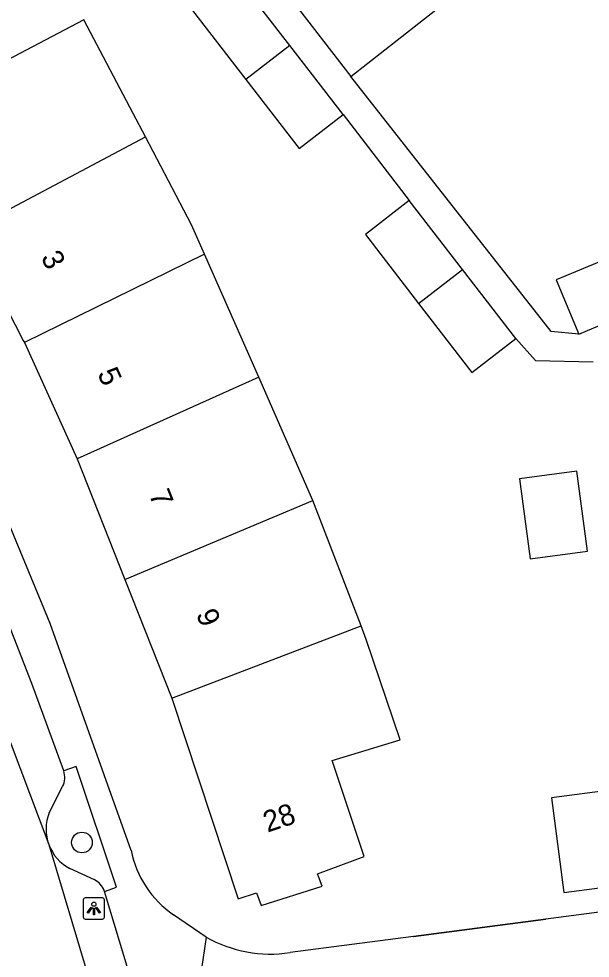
# Model space of a CAD drawing. Extents: x 162074 to 163034, y 381824 to 382557.
# Drawn here: x 162339.63 to 162366.61, y 382465.37 to 382509.72 of the extents above; entities that cross this region are included whole.
import ezdxf

# ---------------------------------------------------------------- set-up
doc = ezdxf.new("R2010")
doc.units = 0
for name, color, linetype in [('IMGEO_Boom', 7, 'Continuous'), ('IMGEO_Lichtpunt', 7, 'Continuous'), ('IMGEO_Muur', 7, 'Continuous'), ('IMGEO_Pand', 7, 'Continuous'), ('IMGEO_Pand_nummerreeks', 7, 'Continuous'), ('IMGEO_Parkeervlak_open', 7, 'Continuous'), ('IMGEO_Rijbaan_lokaal_gesloten', 7, 'Continuous'), ('IMGEO_Voetpad_open', 7, 'Continuous')]:
    doc.layers.add(name, color=color, linetype=linetype)

msp = doc.modelspace()

# ---------------------------------------------------------------- linework, layer by layer
at = {"layer": 'IMGEO_Boom'}
msp.add_circle((162342.613, 382470.834), 0.489, dxfattribs=at)
at = {"layer": 'IMGEO_Lichtpunt'}
for p, q in [((162342.677, 382468.123), (162342.677, 382467.316)), ((162342.677, 382468.123), (162342.677, 382467.316)), ((162343.579, 382468.218), (162342.771, 382468.218)), ((162343.579, 382468.218), (162342.771, 382468.218)), ((162343.673, 382467.316), (162343.673, 382468.123)), ((162343.673, 382467.316), (162343.673, 382468.123)), ((162342.771, 382467.222), (162343.579, 382467.222)), ((162342.771, 382467.222), (162343.579, 382467.222))]:
    msp.add_line(p, q, dxfattribs=at)
for points in [[(162343.051, 382467.787), (162343.09, 382467.759), (162342.902, 382467.497), (162342.864, 382467.524), (162343.051, 382467.787)], [(162343.153, 382467.739), (162343.2, 382467.739), (162343.2, 382467.417), (162343.153, 382467.417), (162343.153, 382467.739)], [(162343.263, 382467.759), (162343.301, 382467.786), (162343.488, 382467.524), (162343.449, 382467.496), (162343.263, 382467.759)]]:
    msp.add_lwpolyline(points, dxfattribs=at)
msp.add_circle((162343.176, 382467.921), 0.0994, dxfattribs=at)
for centre, start, end in [((162342.771, 382468.123), 90, 180), ((162342.771, 382468.123), 90, 180), ((162343.579, 382468.123), 0, 90), ((162343.579, 382468.123), 0, 90), ((162342.771, 382467.316), 180, 270), ((162342.771, 382467.316), 180, 270), ((162343.579, 382467.316), 270, 0), ((162343.579, 382467.316), 270, 360)]:
    msp.add_arc(centre, 0.0946, start, end, dxfattribs=at)
at = {"layer": 'IMGEO_Muur'}
msp.add_lwpolyline([(162358.274, 382466.401), (162364.52, 382467.221)], dxfattribs=at)
at = {"layer": 'IMGEO_Pand'}
for points in [[(162349.248, 382514.857), (162352.301, 382510.897), (162355.304, 382507)], [(162349.916, 382511.715), (162347.84, 382510.115), (162350.351, 382506.857)], [(162352.427, 382508.458), (162349.916, 382511.715)], [(162355.304, 382507), (162360.118, 382510.786)], [(162345.614, 382504.148), (162345.035, 382505.25), (162342.711, 382509.677), (162334.255, 382505.237), (162334.806, 382504.186), (162334.186, 382503.86), (162335.566, 382501.232), (162336.213, 382501.572), (162337.025, 382500), (162337.188, 382499.684)], [(162352.427, 382508.458), (162350.351, 382506.857)], [(162354.939, 382505.198), (162352.427, 382508.458)], [(162350.351, 382506.857), (162352.863, 382503.598), (162354.939, 382505.198)], [(162337.188, 382499.684), (162337.784, 382500), (162345.614, 382504.148)], [(162348.404, 382498.607), (162347.791, 382500), (162345.614, 382504.148)], [(162358.069, 382501.145), (162355.993, 382499.545), (162358.505, 382496.287)], [(162360.58, 382497.888), (162358.069, 382501.145)], [(162337.188, 382499.684), (162339.847, 382494.541), (162339.895, 382494.435)], [(162368.715, 382498.945), (162365.914, 382497.774), (162365.006, 382497.395), (162366.074, 382494.84)], [(162348.404, 382498.607), (162339.895, 382494.435)], [(162350.957, 382492.801), (162348.404, 382498.607)], [(162358.505, 382496.287), (162360.58, 382497.888)], [(162363.092, 382494.628), (162360.58, 382497.888)], [(162358.505, 382496.287), (162361.016, 382493.028), (162363.092, 382494.628)], [(162366.074, 382494.84), (162369.808, 382496.402)], [(162339.895, 382494.435), (162342.396, 382488.941)], [(162350.957, 382492.801), (162342.396, 382488.941)], [(162353.515, 382486.987), (162350.957, 382492.801)], [(162342.396, 382488.941), (162344.642, 382483.25)], [(162363.769, 382484.234), (162366.474, 382484.587), (162365.982, 382488.359), (162363.277, 382488.006), (162363.769, 382484.234)], [(162344.642, 382483.25), (162353.515, 382486.987)], [(162355.79, 382481.061), (162353.515, 382486.987)], [(162344.642, 382483.25), (162346.852, 382477.646)], [(162346.852, 382477.646), (162355.79, 382481.061)], [(162346.852, 382477.646), (162349.986, 382468.167), (162350.847, 382468.463), (162351.075, 382467.853), (162353.947, 382468.78), (162353.729, 382469.361), (162355.932, 382470.181), (162354.43, 382474.706), (162357.631, 382475.682), (162356.035, 382480.422), (162355.79, 382481.061)], [(162365.36, 382468.479), (162368.129, 382468.84), (162367.545, 382473.312), (162364.776, 382472.95), (162365.36, 382468.479)]]:
    msp.add_lwpolyline(points, dxfattribs=at)
at = {"layer": 'IMGEO_Parkeervlak_open'}
for points in [[(162341.072, 382472.235), (162341.7, 382473.471)], [(162343.204, 382469.075), (162342.049, 382469.609)], [(162343.672, 382468.517), (162343.658, 382468.564)]]:
    msp.add_lwpolyline(points, dxfattribs=at)
for centre, radius, start, end in [((162340.864, 382473.906), 0.942, 332.5041, 19.39), ((162342.997, 382471.457), 2.076, 157.9974, 200.321), ((162343.002, 382471.46), 2.082, 200.3477, 242.7614), ((162342.787, 382468.247), 0.927, 19.9834, 63.2558)]:
    msp.add_arc(centre, radius, start, end, dxfattribs=at)
at = {"layer": 'IMGEO_Rijbaan_lokaal_gesloten'}
for points in [[(162335.462, 382485.538), (162341.05, 382470.736)], [(162341.05, 382470.736), (162343.943, 382461.05)]]:
    msp.add_lwpolyline(points, dxfattribs=at)
at = {"layer": 'IMGEO_Voetpad_open'}
for points in [[(162366.074, 382494.84), (162364.77, 382494.958), (162355.304, 382507)], [(162354.939, 382505.198), (162358.069, 382501.145)], [(162363.092, 382494.628), (162364.021, 382493.592), (162366.744, 382493.524)], [(162344.932, 382470.464), (162341.11, 382481.173), (162338.804, 382486.778)], [(162341.753, 382474.219), (162340.252, 382478.334), (162338.208, 382483.555)], [(162441.501, 382477.324), (162364.52, 382467.221), (162358.274, 382466.401), (162352.438, 382465.635)], [(162343.672, 382468.517), (162344.246, 382468.719), (162342.339, 382474.428), (162341.753, 382474.219)], [(162344.851, 382464.666), (162343.672, 382468.517)], [(162348.481, 382466.366), (162346.942, 382467.415)], [(162348.481, 382466.366), (162347.775, 382461.567)]]:
    msp.add_lwpolyline(points, dxfattribs=at)
for centre, radius, start, end in [((162349.678, 382471.406), 4.838, 191.2214, 235.567), ((162351.519, 382471.738), 6.172, 240.5075, 278.5593)]:
    msp.add_arc(centre, radius, start, end, dxfattribs=at)

# ---------------------------------------------------------------- texts
at = {"layer": 'IMGEO_Pand_nummerreeks'}
for s, rotation, p in [('3', 297.2802, (162340.655, 382498.459)), ('5', 294.4772, (162343.325, 382492.982)), ('7', 291.5298, (162345.763, 382487.276)), ('9', 291.5298, (162347.991, 382481.629)), ('28', 18.712, (162351.371, 382471.297))]:
    msp.add_text(s, height=1, rotation=rotation, dxfattribs=at).set_placement(p)

doc.saveas('drawing.dxf')
